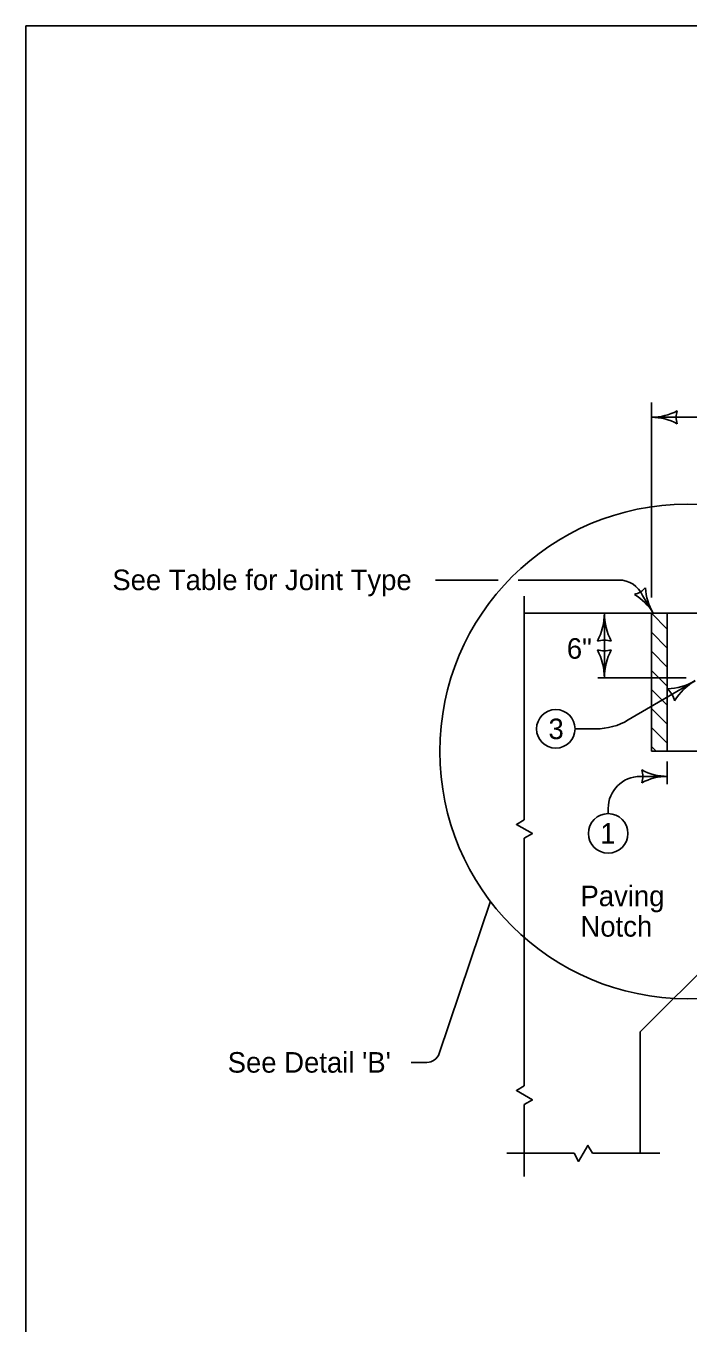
# Model space of a CAD drawing. Extents: x 9234 to 81668, y 5635 to 15999.
# Drawn here: x 10133 to 10648, y 8934 to 9944 of the extents above; entities that cross this region are included whole.
import ezdxf

# ---------------------------------------------------------------- set-up
doc = ezdxf.new("R2010")
doc.units = 0
for name, color, linetype in [('Level 61', 7, 'Continuous'), ('PS_BOLT', 7, 'Continuous'), ('PS_CONST', 7, 'Continuous'), ('PS_DIM', 7, 'Continuous'), ('PS_SHAPE', 7, 'Continuous'), ('PS_TEXT', 7, 'Continuous')]:
    doc.layers.add(name, color=color, linetype=linetype)

msp = doc.modelspace()

# ---------------------------------------------------------------- linework, layer by layer
at = {"layer": 'Level 61'}
msp.add_lwpolyline([(10132.5, 9944), (13267.5, 9944), (13267.5, 7924), (10132.5, 7924)], close=True, dxfattribs=at)
at = {"layer": 'PS_BOLT'}
for p, q in [((10500.1, 9512.6), (10451.4, 9512.6)), ((10594.2, 9512.6), (10515.9, 9512.6)), ((10631.8, 9486.7), (11232.9, 9486.7)), ((10631.8, 9379.4), (10631.8, 9486.7)), ((10631.8, 9353.7), (10631.8, 9371.3)), ((10632, 9359.7), (10610.9, 9359.7)), ((10585.9, 9330.6), (10585.9, 9334.7))]:
    msp.add_line(p, q, dxfattribs=at)
msp.add_lwpolyline([(11232.9, 9486.7), (10631.8, 9486.7), (10631.8, 9379.4), (10699.4, 9379.4), (10699.4, 9387.7), (10832, 9389.1), (10977.7, 9388.6), (11232.9, 9389.3), (11232.9, 9429.9), (11239.1, 9433.5), (11226.6, 9440.8), (11232.9, 9444.4), (11232.9, 9470.4)], close=True, dxfattribs=at)
msp.add_arc((10594.2, 9492.4), 20.2, 23.6401, 90, dxfattribs=at)
at = {"layer": 'PS_CONST'}
for p, q in [((10619.6, 9537.5), (10619.6, 9650.7)), ((10619.6, 9639.3), (11179.4, 9639.3)), ((10619.6, 9499.1), (10619.6, 9537.5)), ((10582.9, 9486.7), (10582.9, 9436.5)), ((10646.6, 9436.5), (10577.9, 9436.5)), ((10653.5, 9434.2), (10601.5, 9403.6)), ((10576.2, 9396.7), (10560.1, 9396.7)), ((10494.2, 9262.5), (10454.3, 9143.9)), ((10444.8, 9137), (10432.6, 9137))]:
    msp.add_line(p, q, dxfattribs=at)
msp.add_circle((10647.3, 9379.1), 192.5, dxfattribs=at)
for centre, radius, start, end in [((10619.6, 9681.8), 42.5, 270, 298.0725), ((10619.6, 9596.8), 42.5, 61.9275, 90), ((10655.2, 9639.3), 16.4, 162.2666, 197.7334), ((10602.4, 9517.3), 16.4, 283.7115, 319.1782), ((10657.3, 9509), 42.5, 183.3724, 211.4449), ((10584.7, 9464.7), 42.5, 31.4449, 59.5174), ((10536.8, 9486.7), 46.1, 331.9275, 360), ((10629, 9486.7), 46.1, 180, 208.0725), ((10582.9, 9448), 17.8, 72.2666, 107.7334), ((10582.9, 9475.2), 17.8, 252.2666, 287.7333), ((10536.8, 9436.5), 46.1, 360, 28.0725), ((10629, 9436.5), 46.1, 151.9275, 180), ((10630.1, 9473.9), 46.1, 272.4041, 300.4766), ((10676.9, 9394.5), 46.1, 120.4766, 148.5491), ((10620.2, 9414.6), 17.8, 12.7432, 48.2099), ((10596.4, 9359.7), 16.4, 342.2666, 17.7333), ((10632, 9402.2), 42.5, 241.9275, 270), ((10632, 9317.2), 42.5, 90, 118.0725)]:
    msp.add_arc(centre, radius, start, end, dxfattribs=at)
at = {"layer": 'PS_DIM'}
for p, q in [((10612.7, 9500.5), (10621, 9486.9)), ((10631.8, 9474.4), (10619.6, 9486.7)), ((10631.8, 9459.6), (10619.6, 9471.9)), ((10631.8, 9444.8), (10619.6, 9457.1)), ((10631.8, 9430), (10619.6, 9442.2)), ((10631.8, 9415.2), (10619.6, 9427.4)), ((10631.8, 9400.4), (10619.6, 9412.6)), ((10631.8, 9385.5), (10619.6, 9397.8)), ((10623.2, 9379.4), (10619.6, 9383))]:
    msp.add_line(p, q, dxfattribs=at)
msp.add_circle((10585.9, 9315.3), 15.4, dxfattribs=at)
for centre, radius, start, end in [((10576.2, 9446.7), 50, 270, 300.4766), ((10610.9, 9334.7), 25, 90, 180), ((10444.8, 9147), 10, 270, 341.4058)]:
    msp.add_arc(centre, radius, start, end, dxfattribs=at)
at = {"layer": 'PS_SHAPE'}
for p, q in [((10520.6, 9500.1), (10520.6, 9415.1)), ((10643.4, 9486.7), (10520.6, 9486.7)), ((10619.6, 9379.4), (10619.6, 9486.7)), ((10520.6, 9415.1), (10520.6, 9325.9)), ((10619.6, 9379.4), (10734.5, 9379.4)), ((10520.6, 9311.5), (10520.6, 9118.7)), ((10610.9, 9160.8), (10734.5, 9284.5)), ((10610.9, 9066.2), (10610.9, 9160.8)), ((10520.6, 9104.2), (10520.6, 9048.2)), ((10559.3, 9066.2), (10506.9, 9066.2)), ((10626.2, 9066.2), (10573.7, 9066.2))]:
    msp.add_line(p, q, dxfattribs=at)
for points in [[(10520.6, 9311.5), (10526.9, 9315.1), (10514.4, 9322.3), (10520.6, 9325.9)], [(10520.6, 9104.2), (10526.9, 9107.8), (10514.4, 9115.1), (10520.6, 9118.7)], [(10573.7, 9066.2), (10570.1, 9072.4), (10562.9, 9059.9), (10559.3, 9066.2)]]:
    msp.add_lwpolyline(points, dxfattribs=at)
at = {"layer": 'PS_TEXT'}
msp.add_circle((10545.1, 9396.7), 15, dxfattribs=at)

# ---------------------------------------------------------------- texts
at = {"layer": 'PS_BOLT'}
msp.add_text('1', height=16, dxfattribs=at).set_placement((10579.7, 9307.3))
at = {"layer": 'PS_CONST'}
for s, p in [('See Table for Joint Type', (10199.8, 9504.7)), ('6"', (10553.7, 9451.3)), ('Paving', (10564.3, 9258.6)), ('Notch', (10564.3, 9234.9)), ("See Detail 'B'", (10289.6, 9129))]:
    msp.add_text(s, height=16, dxfattribs=at).set_placement(p)
at = {"layer": 'PS_TEXT'}
msp.add_text('3', height=16, dxfattribs=at).set_placement((10539.4, 9388.7))

doc.saveas('drawing.dxf')
